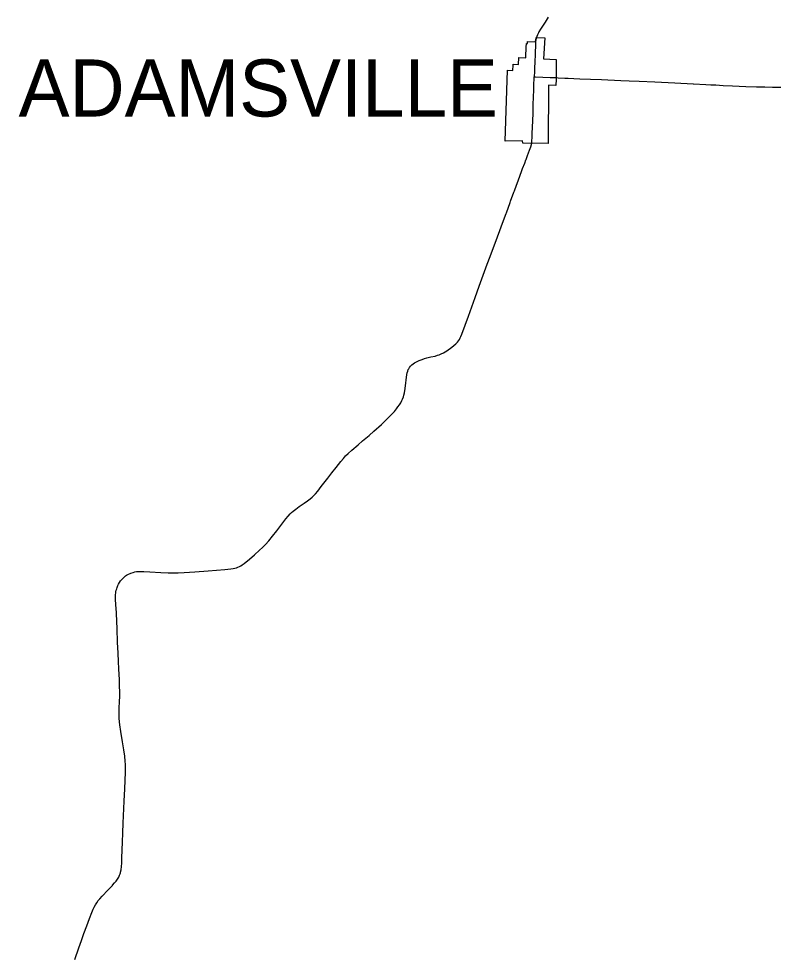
# Model space of a CAD drawing. Extents: x 2015843 to 2287843, y 623733 to 799733.
# Drawn here: x 2146170 to 2161112, y 732143 to 750540 of the extents above; entities that cross this region are included whole.
import ezdxf

# ---------------------------------------------------------------- set-up
doc = ezdxf.new("R2010")
doc.units = 0
for name, color, linetype in [('GM_X_Corporation', 7, 'Continuous'), ('GM_X_Corporation_Text', 7, 'Continuous'), ('GM_X_State_Route', 7, 'Continuous')]:
    doc.layers.add(name, color=color, linetype=linetype)

msp = doc.modelspace()

# ---------------------------------------------------------------- linework, layer by layer
at = {"layer": 'GM_X_Corporation'}
msp.add_lwpolyline([(2155712, 748140), (2155763, 749529), (2155864, 749527), (2155870, 749627), (2155872, 749651), (2155974, 749645), (2155983, 749777), (2156118, 749773), (2156125, 750001), (2156128, 750017), (2156130, 750025), (2156130, 750034), (2156131, 750053), (2156150, 750053), (2156152, 750093), (2156309, 750086), (2156315, 750133), (2156320, 750156), (2156325, 750174), (2156490, 750167), (2156465, 749753), (2156718, 749739), (2156717, 749386), (2156717, 749351), (2156710, 749233), (2156566, 749236), (2156560, 748090), (2156059, 748098), (2156057, 748143)], close=True, dxfattribs=at)
at = {"layer": 'GM_X_State_Route'}
for points in [[(2156557, 750572), (2156497, 750475), (2156410, 750336), (2156377, 750280), (2156368, 750265), (2156346, 750221), (2156333, 750191), (2156323, 750161)], [(2156308, 750056), (2156307, 750034), (2156307, 750031), (2156301, 749866), (2156294, 749670), (2156291, 749599), (2156288, 749507), (2156286, 749401)], [(2156323, 750161), (2156321, 750153), (2156316, 750130), (2156310, 750083), (2156308, 750056)], [(2156256, 748530), (2156262, 748693), (2156266, 748812), (2156273, 749050), (2156275, 749097), (2156279, 749214), (2156286, 749401)], [(2156286, 749401), (2156310, 749400), (2156600, 749390), (2156691, 749386), (2156710, 749385)], [(2156710, 749385), (2156753, 749383), (2156884, 749376), (2156949, 749373), (2157064, 749367), (2157178, 749362), (2157391, 749355), (2157604, 749347), (2157981, 749329), (2158145, 749321), (2158341, 749313), (2158653, 749300), (2159046, 749281), (2159406, 749262), (2159413, 749261), (2159651, 749250), (2159750, 749246), (2159848, 749241), (2159995, 749233), (2160174, 749225), (2160305, 749218), (2160435, 749211), (2160648, 749205), (2160812, 749201), (2160959, 749199), (2161123, 749197)], [(2156234, 748088), (2156235, 748094), (2156238, 748123), (2156239, 748142), (2156243, 748207), (2156244, 748250), (2156253, 748451), (2156254, 748498), (2156256, 748530)], [(2148312, 739636), (2148367, 739660), (2148414, 739676), (2148446, 739684), (2148479, 739690), (2148512, 739694), (2148561, 739696), (2148627, 739694), (2148742, 739686), (2148955, 739673), (2149102, 739667), (2149200, 739665), (2149299, 739666), (2149413, 739671), (2149626, 739685), (2149888, 739705), (2150215, 739733), (2150329, 739743), (2150377, 739751), (2150409, 739758), (2150440, 739767), (2150470, 739778), (2150500, 739791), (2150528, 739807), (2150556, 739824), (2150595, 739853), (2150697, 739936), (2150796, 740022), (2150894, 740109), (2150953, 740166), (2150984, 740198), (2151010, 740225), (2151075, 740298), (2151150, 740385), (2151232, 740491), (2151331, 740621), (2151410, 740725), (2151455, 740780), (2151498, 740827), (2151520, 740849), (2151556, 740879), (2151608, 740919), (2151675, 740966), (2151770, 741031), (2151836, 741078), (2151888, 741117), (2151925, 741149), (2151961, 741183), (2151994, 741218), (2152036, 741268), (2152107, 741358), (2152236, 741527), (2152316, 741631), (2152396, 741734), (2152487, 741850), (2152540, 741913), (2152584, 741962), (2152631, 742008), (2152705, 742074), (2152830, 742180), (2152917, 742254), (2153043, 742363), (2153140, 742448), (2153285, 742580), (2153369, 742658), (2153440, 742726), (2153497, 742784), (2153541, 742833), (2153582, 742884), (2153611, 742923), (2153639, 742963), (2153665, 743004), (2153688, 743047), (2153701, 743077), (2153718, 743122), (2153727, 743154), (2153737, 743201), (2153751, 743287), (2153787, 743558), (2153794, 743591), (2153802, 743623), (2153814, 743654), (2153821, 743669), (2153838, 743698), (2153858, 743724), (2153881, 743748), (2153907, 743769), (2153936, 743789), (2153975, 743809), (2154024, 743831), (2154085, 743855), (2154129, 743870), (2154176, 743884), (2154258, 743904), (2154338, 743921), (2154385, 743935), (2154422, 743947), (2154458, 743962), (2154503, 743986), (2154567, 744025), (2154669, 744096), (2154708, 744128), (2154747, 744162), (2154776, 744194), (2154797, 744219), (2154816, 744247), (2154833, 744276), (2154847, 744305), (2154867, 744350), (2154993, 744701), (2155126, 745073), (2155205, 745292), (2155363, 745721), (2155421, 745874), (2155563, 746258), (2155682, 746582), (2155734, 746721), (2155738, 746732), (2155812, 746936), (2155821, 746961), (2155885, 747137), (2155895, 747162), (2155938, 747275), (2155968, 747362), (2156043, 747561), (2156057, 747598), (2156098, 747704), (2156122, 747770), (2156126, 747780), (2156154, 747856), (2156194, 747962), (2156215, 748024), (2156229, 748071), (2156233, 748083), (2156234, 748088)], [(2148166, 733782), (2148168, 733793), (2148178, 733841), (2148186, 733905), (2148191, 733971), (2148194, 734069), (2148199, 734234), (2148206, 734381), (2148212, 734562), (2148218, 734757), (2148236, 735184), (2148248, 735430), (2148263, 735756), (2148266, 735839), (2148266, 735904), (2148261, 735969), (2148249, 736067), (2148229, 736196), (2148203, 736350), (2148171, 736553), (2148151, 736682), (2148145, 736741), (2148141, 736814), (2148141, 736894), (2148143, 737026), (2148148, 737131), (2148151, 737256), (2148151, 737339), (2148149, 737437), (2148144, 737569), (2148134, 737780), (2148127, 737929), (2148120, 738093), (2148110, 738305), (2148098, 738566), (2148088, 738868), (2148087, 738879), (2148076, 739043), (2148071, 739144), (2148068, 739205), (2148070, 739241), (2148072, 739268), (2148077, 739297), (2148083, 739326), (2148091, 739354), (2148099, 739379), (2148107, 739400), (2148116, 739421), (2148129, 739447), (2148148, 739480), (2148168, 739508), (2148205, 739550), (2148237, 739583), (2148266, 739605), (2148284, 739618), (2148312, 739636)], [(2148012, 733538), (2148051, 733582), (2148079, 733616), (2148107, 733655), (2148132, 733696), (2148149, 733731), (2148160, 733761), (2148166, 733782)], [(2147271, 732076), (2147350, 732309), (2147399, 732449), (2147448, 732588), (2147505, 732742), (2147556, 732881), (2147602, 733004), (2147627, 733064), (2147649, 733109), (2147673, 733152), (2147699, 733194), (2147728, 733234), (2147760, 733272), (2147804, 733321), (2147917, 733439), (2148008, 733533), (2148012, 733538)]]:
    msp.add_lwpolyline(points, dxfattribs=at)

# ---------------------------------------------------------------- texts
at = {"layer": 'GM_X_Corporation_Text'}
msp.add_text('ADAMSVILLE', height=1120, rotation=0, dxfattribs=at).set_placement((2146167, 748621))

doc.saveas('drawing.dxf')
